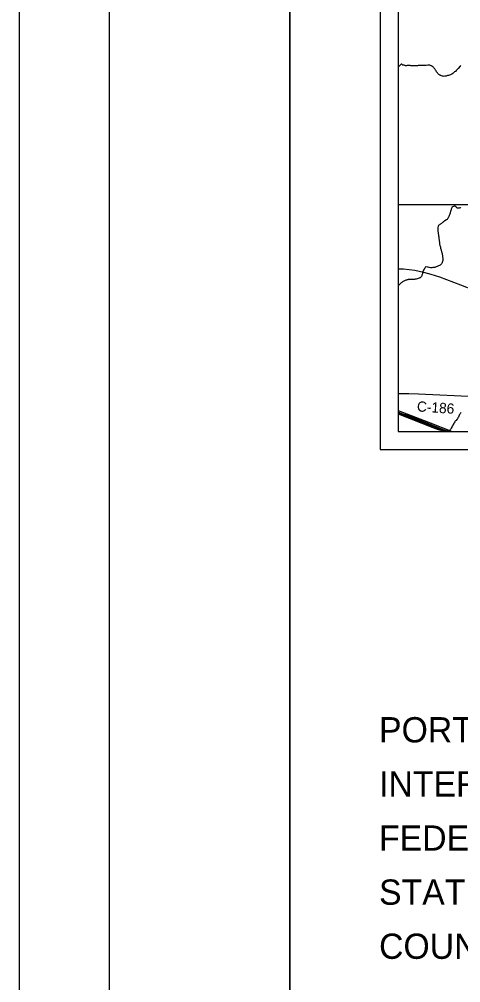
# Model space of a CAD drawing. Extents: x 0 to 34, y 0 to 22.
# Drawn here: x 0 to 2.45, y 11.04 to 16.39 of the extents above; entities that cross this region are included whole.
import ezdxf

# ---------------------------------------------------------------- set-up
doc = ezdxf.new("R2010")
doc.units = 0
for name, color, linetype in [('GM_X_Corporation', 7, 'Continuous'), ('GM_X_County_Road', 7, 'Continuous'), ('GM_X_County_Road_Text', 7, 'Continuous'), ('GM_X_Minor_River', 7, 'Continuous'), ('GM_X_Rail_Line', 7, 'Continuous'), ('GM_X_State_Route', 7, 'Continuous'), ('SH_Border', 7, 'Continuous'), ('SH_Cut_Line', 7, 'Continuous'), ('SH_Data', 7, 'Continuous'), ('SH_Text', 7, 'Continuous')]:
    doc.layers.add(name, color=color, linetype=linetype)

msp = doc.modelspace()

# ---------------------------------------------------------------- linework, layer by layer
at = {"layer": 'GM_X_Corporation'}
for points in [[(2.1, 20.3879), (2.1, 14.1), (7.1335, 14.1), (7.1269, 14.4049), (7.1267, 14.4123), (7.1215, 14.6514), (7.118, 14.8105), (7.1072, 15.3824), (7.0838, 16.6084)], [(2.1, 20.3879), (2.1, 15.3574), (2.6127, 15.3592), (3.4135, 15.3624), (4.1534, 15.3654), (4.1554, 15.3654), (5.1944, 15.3696), (5.8313, 15.3671), (6.0415, 15.3685), (7.1072, 15.3824), (7.0838, 16.6084)]]:
    msp.add_lwpolyline(points, dxfattribs=at)
msp.add_lwpolyline([(2.1, 15.3574), (2.1, 14.1), (7.1335, 14.1), (7.1269, 14.4049), (7.1267, 14.4123), (7.1215, 14.6514), (7.118, 14.8105), (7.1072, 15.3824), (6.0415, 15.3685), (5.8313, 15.3671), (5.1944, 15.3696), (4.1554, 15.3654), (4.1534, 15.3654), (3.4135, 15.3624), (2.6127, 15.3592)], close=True, dxfattribs=at)
at = {"layer": 'GM_X_County_Road'}
msp.add_lwpolyline([(2.1, 14.3107), (2.122, 14.3108), (2.1603, 14.3107), (2.2123, 14.3096), (2.5299, 14.2946)], dxfattribs=at)
at = {"layer": 'GM_X_Minor_River'}
for points in [[(2.4125, 16.0943), (2.4102, 16.092), (2.4071, 16.089), (2.4025, 16.0845), (2.3975, 16.0812), (2.3941, 16.0801), (2.3899, 16.0782), (2.3857, 16.0764), (2.3796, 16.0749), (2.3738, 16.0738), (2.3655, 16.0713), (2.3594, 16.0702), (2.3544, 16.0695), (2.3499, 16.0699), (2.3453, 16.0708), (2.3408, 16.0723), (2.3377, 16.0735), (2.3355, 16.0747), (2.3332, 16.0758), (2.3305, 16.077), (2.3287, 16.0782), (2.3264, 16.0797), (2.3238, 16.0809), (2.3223, 16.0828), (2.32, 16.0859), (2.3178, 16.0882), (2.3159, 16.0905), (2.3144, 16.0932), (2.3129, 16.0951), (2.3103, 16.0993), (2.3077, 16.1031), (2.3054, 16.1066), (2.3028, 16.1112), (2.301, 16.1135), (2.298, 16.1169), (2.2957, 16.1192), (2.2938, 16.1215), (2.2912, 16.1239), (2.2889, 16.1258), (2.287, 16.1266), (2.2852, 16.1273), (2.2833, 16.1277), (2.2761, 16.1313), (2.2708, 16.1317), (2.2639, 16.131), (2.2559, 16.13), (2.2498, 16.1297), (2.2426, 16.1298), (2.2369, 16.1298), (2.2323, 16.1299), (2.2282, 16.1295), (2.2236, 16.1288), (2.219, 16.1289), (2.2156, 16.1289), (2.2118, 16.129), (2.2076, 16.1286), (2.203, 16.1276), (2.1989, 16.1272), (2.1954, 16.1277), (2.189, 16.1281), (2.1818, 16.1282), (2.1749, 16.1283), (2.17, 16.1287), (2.1662, 16.1295), (2.1628, 16.1299), (2.159, 16.1296), (2.1555, 16.1293), (2.151, 16.1289), (2.146, 16.1282), (2.1434, 16.1283), (2.1407, 16.1287), (2.1388, 16.1295), (2.1369, 16.1302), (2.1339, 16.131), (2.1312, 16.1318), (2.1278, 16.1319), (2.1255, 16.1319), (2.1241, 16.1338), (2.1199, 16.1362), (2.1165, 16.1373), (2.1146, 16.1358), (2.108, 16.1279), (2.1042, 16.1246), (2.1, 16.1201)], [(2.4483, 16.13), (2.444, 16.1251), (2.4332, 16.1134), (2.4298, 16.1093), (2.4259, 16.1051), (2.4217, 16.1018), (2.4178, 16.0969), (2.4125, 16.0943)], [(2.4479, 15.3416), (2.4456, 15.3413), (2.4437, 15.3405), (2.4414, 15.3398), (2.4391, 15.3395), (2.4365, 15.3387), (2.4334, 15.3384), (2.4296, 15.3392), (2.4262, 15.3411), (2.4229, 15.3438), (2.4195, 15.3469), (2.4161, 15.35), (2.4123, 15.3523), (2.41, 15.3504), (2.4062, 15.3478), (2.4012, 15.3452), (2.3985, 15.3434), (2.397, 15.3411), (2.3958, 15.3377), (2.3946, 15.3339), (2.3934, 15.3301), (2.3922, 15.3252), (2.391, 15.321), (2.3899, 15.318), (2.389, 15.3142), (2.3879, 15.3104), (2.3867, 15.3059), (2.3847, 15.3017), (2.3831, 15.2975), (2.3812, 15.2934)], [(2.3812, 15.2934), (2.3792, 15.2888), (2.3777, 15.2858), (2.3765, 15.2836), (2.375, 15.2809), (2.3734, 15.2787), (2.3711, 15.2764), (2.368, 15.2742), (2.3588, 15.2689), (2.3562, 15.2667), (2.3531, 15.2645), (2.3504, 15.2622), (2.3473, 15.2592), (2.3443, 15.2566), (2.3408, 15.254), (2.3377, 15.2517), (2.3343, 15.2495), (2.3316, 15.248), (2.3297, 15.2457), (2.3266, 15.2439), (2.3243, 15.242), (2.3212, 15.2397), (2.3208, 15.2321), (2.32, 15.2284), (2.3195, 15.2242), (2.3195, 15.2208), (2.3195, 15.217), (2.3202, 15.2128), (2.3209, 15.209), (2.3216, 15.2048), (2.3223, 15.2006), (2.3226, 15.1964), (2.3233, 15.1918), (2.3248, 15.185), (2.3255, 15.1796), (2.3262, 15.1743), (2.3265, 15.169), (2.3268, 15.1644), (2.3282, 15.156), (2.3286, 15.1526), (2.3293, 15.1488), (2.33, 15.1442), (2.3303, 15.1397), (2.3318, 15.1359), (2.3321, 15.132), (2.3332, 15.1275), (2.3347, 15.1225), (2.3357, 15.1172), (2.3372, 15.1122), (2.3383, 15.108), (2.3394, 15.1046), (2.3405, 15.1008), (2.3412, 15.097), (2.3423, 15.0924), (2.3437, 15.0867), (2.3445, 15.084), (2.3448, 15.0813), (2.3455, 15.0779), (2.3459, 15.0741), (2.3466, 15.0703), (2.3469, 15.0669), (2.3473, 15.0635), (2.3476, 15.0608), (2.3479, 15.0574), (2.3479, 15.0543), (2.3479, 15.0517), (2.3475, 15.0479), (2.3463, 15.0433), (2.3447, 15.0399), (2.3435, 15.0361), (2.3416, 15.0331), (2.3396, 15.0293), (2.3373, 15.0271), (2.3354, 15.0252), (2.3327, 15.023), (2.3289, 15.0203), (2.3239, 15.0181), (2.317, 15.0152), (2.3117, 15.0133), (2.3071, 15.0119), (2.3029, 15.0104), (2.2979, 15.0093), (2.2922, 15.009), (2.2862, 15.0087), (2.2797, 15.0088), (2.2729, 15.0092), (2.2672, 15.0108), (2.2622, 15.012), (2.252, 15.0129), (2.25, 15.0072), (2.247, 15.0046), (2.2446, 15.0008), (2.2408, 14.9948), (2.2388, 14.9914), (2.2361, 14.9834), (2.2352, 14.9796), (2.2344, 14.9755), (2.2336, 14.9717), (2.2324, 14.9671), (2.2312, 14.963), (2.2301, 14.9607)], [(2.2301, 14.9607), (2.2285, 14.9584), (2.2262, 14.9558), (2.2239, 14.9536), (2.222, 14.9528), (2.2197, 14.9517), (2.2163, 14.9502), (2.2117, 14.9491), (2.2064, 14.9477), (2.1995, 14.9459), (2.1953, 14.9448), (2.1907, 14.9437), (2.1858, 14.9434), (2.1804, 14.943), (2.1747, 14.9427), (2.1694, 14.9432), (2.1641, 14.9432), (2.1603, 14.9433), (2.1576, 14.9429), (2.1557, 14.9426), (2.1534, 14.9418), (2.15, 14.9407), (2.147, 14.94), (2.1431, 14.9389), (2.1389, 14.9378), (2.1351, 14.9364), (2.1271, 14.9323), (2.1236, 14.9297), (2.1202, 14.9274), (2.1175, 14.9248), (2.1129, 14.921), (2.1094, 14.918), (2.1064, 14.9143), (2.1033, 14.9109), (2.101, 14.9075), (2.1, 14.9063)], [(2.4406, 14.1939), (2.439, 14.1905), (2.4343, 14.1807), (2.4324, 14.178), (2.4316, 14.1758), (2.4293, 14.1716), (2.4258, 14.1663), (2.4216, 14.1622), (2.4181, 14.16), (2.4162, 14.1585), (2.4135, 14.1532), (2.4111, 14.149), (2.4084, 14.1441), (2.4053, 14.1392), (2.4026, 14.1347), (2.4007, 14.1309), (2.3987, 14.1275), (2.3972, 14.1237), (2.3944, 14.1188), (2.3921, 14.1147), (2.3902, 14.112), (2.3882, 14.109), (2.3859, 14.1068), (2.384, 14.1053), (2.3809, 14.1026), (2.3786, 14.1008), (2.378, 14.1)], [(2.4491, 14.2063), (2.4456, 14.2018), (2.4433, 14.1992), (2.4417, 14.1969), (2.4406, 14.1939)]]:
    msp.add_lwpolyline(points, dxfattribs=at)
at = {"layer": 'GM_X_Rail_Line'}
for p, q in [((2.3537, 14.1038), (2.1, 14.2054)), ((2.3366, 14.1076), (2.3537, 14.1038)), ((2.3537, 14.1038), (2.3652, 14.1))]:
    msp.add_line(p, q, dxfattribs=at)
for points in [[(2.1, 14.2163), (2.2676, 14.1513), (2.4002, 14.1)], [(2.374, 14.1), (2.3668, 14.1022), (2.3353, 14.1135), (2.1, 14.2082)], [(2.1, 14.2025), (2.3058, 14.1207), (2.3366, 14.1076)], [(2.1, 14.1993), (2.2923, 14.1229), (2.3215, 14.1109), (2.3366, 14.1076)], [(2.3862, 14.1), (2.3739, 14.1029), (2.3522, 14.11), (2.137, 14.1972)]]:
    msp.add_lwpolyline(points, dxfattribs=at)
at = {"layer": 'GM_X_State_Route'}
msp.add_lwpolyline([(2.1, 15.0031), (2.1295, 15.0019), (2.193, 14.9952), (2.2415, 14.9847), (2.2821, 14.9733), (2.3296, 14.9574), (2.4458, 14.9138), (2.5214, 14.8849)], dxfattribs=at)
at = {"layer": 'SH_Border'}
for points in [[(0.5, 21.5), (1.5, 21.5), (1.5, 0.5), (0.5, 0.5)], [(1.5, 21.5), (33.5, 21.5), (33.5, 0.5), (1.5, 0.5)]]:
    msp.add_lwpolyline(points, close=True, dxfattribs=at)
at = {"layer": 'SH_Cut_Line'}
msp.add_lwpolyline([(0, 0), (34, 0), (34, 22), (0, 22)], close=True, dxfattribs=at)
at = {"layer": 'SH_Data'}
for p, q in [((2, 21), (2, 14)), ((2.1, 20.9), (2.1, 14.1)), ((2.1, 14.1), (8.9, 14.1)), ((2.1, 14.1), (2.1, 14.1)), ((2, 14), (9, 14))]:
    msp.add_line(p, q, dxfattribs=at)

# ---------------------------------------------------------------- texts
at = {"layer": 'GM_X_County_Road_Text'}
msp.add_text('C-186', height=0.05682, rotation=356.1494, dxfattribs=at).set_placement((2.2031, 14.212))
at = {"layer": 'SH_Text'}
for s, p in [('PORTION TO BE IMPROVED', (1.9944, 12.3767)), ('INTERSTATE HIGHWAY', (1.9944, 12.0767)), ('FEDERAL ROUTES', (1.9944, 11.7767)), ('STATE ROUTES', (1.9944, 11.4767)), ('COUNTY & TOWNSHIP ROADS', (1.9944, 11.1767))]:
    msp.add_text(s, height=0.14, dxfattribs=at).set_placement(p)

doc.saveas('drawing.dxf')
